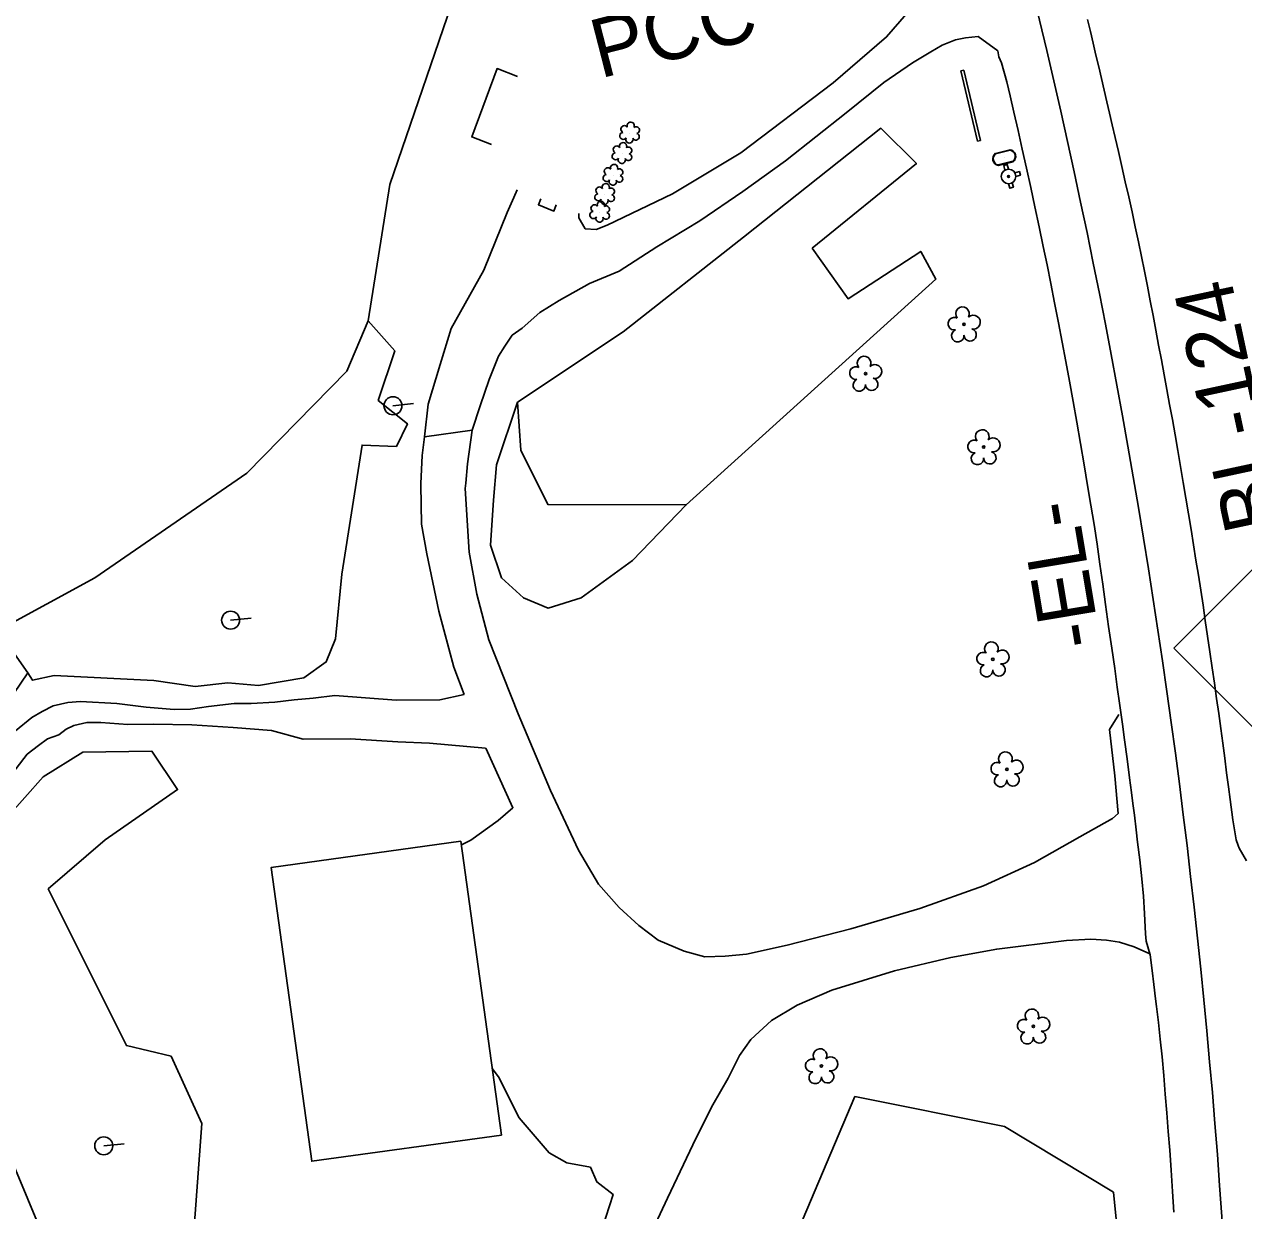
# Model space of a CAD drawing. Extents: x 471894 to 476235, y 503501 to 507878.
# Drawn here: x 474193.2 to 474525.3, y 504600 to 504923.2 of the extents above; entities that cross this region are included whole.
import ezdxf

# ---------------------------------------------------------------- set-up
doc = ezdxf.new("R2010")
doc.units = 0
for name, color, linetype in [('CTL Secondary Horizontal and Vertical CELL', 7, 'Continuous'), ('CTL Secondary Horizontal and Vertical Text', 7, 'Continuous'), ('Exist Building Metal Canopy', 7, 'Continuous'), ('Exist Horizontal Alignment', 7, 'Continuous'), ('Exist Horizontal Alignment Direction Label', 7, 'Continuous'), ('Exist Other Culture Area Outline', 7, 'Continuous'), ('Exist Roads EOP', 7, 'Continuous'), ('Exist Roads EOP Other', 7, 'Continuous'), ('Exist Roads Soil', 7, 'Continuous'), ('Exist Structure Minor Head and End Wall', 7, 'Continuous'), ('Exist Utilities Power Pole CELL', 7, 'Continuous'), ('Exist Utilities Water Fire Hydrant CELL', 7, 'Continuous'), ('Exist Utilities Water Meter CELL', 7, 'Continuous'), ('Exist Vegetation Hedge Row', 7, 'Continuous'), ('Exist Vegetation Shrub CELL', 7, 'Continuous'), ('Exist Vegetation Tree CELL', 7, 'Continuous'), ('Exist Vegetation Woods Line', 7, 'Continuous')]:
    doc.layers.add(name, color=color, linetype=linetype)

msp = doc.modelspace()

# ---------------------------------------------------------------- linework, layer by layer
at = {"layer": 'CTL Secondary Horizontal and Vertical CELL'}
msp.add_lwpolyline([(474506.26, 504753.23), (474532.47, 504779.43), (474558.72, 504753.18), (474532.51, 504726.98)], close=True, dxfattribs=at)
at = {"layer": 'Exist Building Metal Canopy'}
msp.add_lwpolyline([(474312.1, 504700.6), (474323.15, 504620.54), (474271.47, 504613.41), (474260.43, 504693.48)], close=True, dxfattribs=at)
at = {"layer": 'Exist Horizontal Alignment'}
msp.add_arc((472536.78, 504463.34), 1987.17, 358.7675, 14.39186, dxfattribs=at)
at = {"layer": 'Exist Other Culture Area Outline'}
for points in [[(474327.49, 504908.96), (474321.96, 504911.14), (474315.07, 504892.53), (474320.47, 504890.46)], [(474338.07, 504874.06), (474337.44, 504872.33), (474333.21, 504874.07), (474333.89, 504875.65)]]:
    msp.add_lwpolyline(points, dxfattribs=at)
at = {"layer": 'Exist Roads EOP'}
for points in [[(474482.78, 504924.51), (474483.55, 504921.3), (474484.32, 504918.08), (474485.08, 504914.86), (474485.84, 504911.63), (474486.59, 504908.43), (474487.32, 504905.26), (474488.05, 504902.13), (474488.77, 504899.04), (474489.52, 504895.83), (474490.32, 504892.34), (474491.19, 504888.57), (474492.11, 504884.51), (474493.06, 504880.34), (474493.99, 504876.19), (474494.9, 504872.09), (474495.79, 504868.02), (474496.65, 504863.97), (474497.49, 504859.94), (474498.3, 504855.92), (474499.08, 504851.91), (474499.85, 504847.9), (474500.61, 504843.88), (474501.37, 504839.85), (474502.13, 504835.81), (474502.89, 504831.77), (474503.65, 504827.72), (474504.39, 504823.67), (474505.14, 504819.62), (474505.88, 504815.52), (474506.62, 504811.35), (474507.36, 504807.1), (474508.11, 504802.77), (474508.85, 504798.41), (474509.57, 504794.1), (474510.28, 504789.83), (474510.97, 504785.59), (474511.65, 504781.4), (474512.32, 504777.24), (474512.97, 504773.13), (474513.6, 504769.05), (474514.23, 504764.96), (474514.86, 504760.79), (474515.49, 504756.54), (474516.12, 504752.22), (474516.74, 504747.9), (474517.34, 504743.66), (474517.93, 504739.51), (474518.5, 504735.43), (474519.05, 504731.38), (474519.6, 504727.34), (474520.13, 504723.3), (474520.65, 504719.25), (474521.15, 504715.41), (474521.6, 504712), (474522.35, 504706.45), (474523.22, 504701.02), (474523.76, 504699.47), (474524.11, 504698.7), (474526.11, 504695.31)], [(474506.3, 504599.55), (474505.93, 504605.16), (474505.54, 504610.97), (474505.15, 504616.45), (474504.74, 504621.57), (474504.34, 504626.63), (474503.95, 504631.69), (474503.52, 504636.77), (474503.06, 504641.84), (474502.58, 504646.69), (474502.08, 504651.27), (474501.56, 504655.59), (474501.3, 504657.65), (474500.8, 504661.61), (474500.37, 504665.37), (474499.83, 504669.71), (474498.78, 504673.41), (474498.54, 504675.41), (474498.32, 504680.95), (474498.05, 504685.61), (474497.6, 504690.4), (474497.01, 504695.59), (474496.42, 504700.4), (474496.01, 504703.76), (474495.55, 504707.7), (474495.14, 504710.91), (474494.75, 504713.88), (474494.21, 504717.93), (474493.53, 504723.04), (474492.84, 504728.23), (474492.27, 504732.5), (474491.48, 504738.29), (474490.88, 504742.61), (474490.18, 504747.67), (474489.39, 504753.27), (474488.53, 504759.18), (474487.68, 504765.09), (474486.91, 504770.67), (474486.16, 504776.11), (474485.37, 504781.56), (474484.54, 504786.96), (474483.7, 504792.22), (474482.81, 504797.57), (474481.83, 504803.23), (474480.83, 504809.03), (474479.85, 504814.79), (474478.87, 504820.46), (474477.87, 504826), (474476.86, 504831.39), (474475.86, 504836.64), (474474.85, 504841.89), (474473.81, 504847.29), (474472.77, 504852.61), (474471.76, 504857.65), (474470.72, 504862.7), (474469.6, 504868.06), (474468.45, 504873.5), (474467.3, 504878.79), (474466.16, 504883.99), (474465.01, 504889.18), (474463.87, 504894.29), (474462.73, 504899.24), (474461.68, 504903.75), (474460.76, 504907.52), (474459.34, 504912.77), (474459.02, 504913.56), (474458.62, 504914.33), (474458.33, 504916)]]:
    msp.add_lwpolyline(points, dxfattribs=at)
at = {"layer": 'Exist Roads EOP Other'}
for p, q in [((474326.55, 504875.99), (474327.4, 504878.12)), ((474315.2, 504812.65), (474302.17, 504810.79))]:
    msp.add_line(p, q, dxfattribs=at)
for points in [[(474345.92, 504867.53), (474348.98, 504867.32), (474351.93, 504868.46), (474369.71, 504876.99), (474388.35, 504888.21), (474413.53, 504907.31), (474428.05, 504919.81), (474436.49, 504929.49), (474441.42, 504937.69), (474444.56, 504945.08), (474446.91, 504953.55)], [(474315.2, 504812.65), (474317.34, 504819.3), (474319.78, 504826.45), (474322.37, 504832.77), (474324.1, 504835.56), (474326.08, 504838.49), (474328.8, 504840.43), (474333.61, 504844.69), (474338.85, 504847.94), (474347.15, 504852.57), (474355.17, 504855.94), (474365.42, 504862.56), (474377.22, 504869.67), (474388.89, 504877.71), (474400.51, 504885.98), (474417, 504899.13), (474427.29, 504907.38), (474435.09, 504912.72), (474440.11, 504915.76), (474443.17, 504917.56), (474446.84, 504919.04), (474449.51, 504919.52), (474452.99, 504919.92)], [(474458.33, 504916), (474452.99, 504919.92)], [(474302.17, 504810.79), (474303.22, 504819.7), (474306.45, 504830.52), (474309.42, 504840.34), (474318.35, 504856.19), (474324.71, 504871.97), (474326.55, 504875.99)], [(474344.24, 504871.71), (474344.24, 504870.47), (474345.92, 504867.53)]]:
    msp.add_lwpolyline(points, dxfattribs=at)
at = {"layer": 'Exist Roads Soil'}
for points in [[(474313.43, 504798.23), (474313.93, 504803.5), (474315.2, 504812.65)], [(474301.2, 504798.13), (474301.48, 504803.8), (474301.57, 504805.77), (474302.17, 504810.79)], [(474301.33, 504787.04), (474301.18, 504797.72), (474301.2, 504798.13)], [(474313.29, 504796.73), (474313.43, 504798.23)], [(474313.29, 504796.73), (474314.32, 504779.35), (474316.43, 504767.92), (474319.74, 504755.52), (474327.73, 504735.36), (474336.53, 504714.42), (474344.1, 504698.18), (474349.61, 504688.92), (474355.19, 504682.57), (474360.56, 504677.66), (474365.86, 504673.71), (474372.89, 504670.64), (474378.53, 504669.1), (474384.07, 504669.34), (474389.85, 504669.82), (474401, 504672.33), (474418.32, 504676.73), (474437.13, 504682.25), (474454.44, 504688.43), (474468.34, 504694.87), (474480.7, 504701.85), (474489.61, 504706.84), (474491.1, 504708.2), (474490.18, 504718.46), (474488.8, 504731.08), (474491.34, 504735.12)], [(474312.98, 504740.61), (474310.21, 504748.05), (474306.12, 504763.32), (474302.82, 504778.95), (474301.33, 504787.04)], [(474208.48, 504738.66), (474218.42, 504738.16), (474226.4, 504737.18), (474234.01, 504736.49), (474238.48, 504736.58), (474243.39, 504737.34), (474250.36, 504738.15), (474254.97, 504738.11), (474261.42, 504738.49), (474266.69, 504739.11), (474271.84, 504739.59), (474277.73, 504740.35)], [(474277.73, 504740.35), (474294.47, 504739.05), (474306.34, 504739.15), (474312.98, 504740.61)], [(474173.69, 504709.24), (474182.2, 504722.26), (474186.67, 504727.32), (474190.8, 504730.75), (474195.25, 504734.37), (474198.02, 504736), (474201.01, 504737.48), (474205.04, 504738.41), (474208.48, 504738.66)], [(474294.93, 504727.68), (474281.97, 504728.49), (474269.14, 504728.46), (474260.53, 504730.84), (474250.05, 504731.58), (474238.85, 504732.34), (474228.39, 504732.55), (474221.36, 504732.46), (474214, 504732.96), (474210.18, 504732.95), (474206.64, 504732.2)], [(474181.88, 504707.45), (474186.64, 504714.69), (474191, 504720.41), (474194, 504724.32), (474197.04, 504726.68), (474199.51, 504728.56), (474202.59, 504729.66), (474204.59, 504731.12), (474206.64, 504732.2)], [(474294.93, 504727.68), (474303.55, 504727.39), (474318.79, 504725.96)], [(474312.24, 504699.63), (474314.8, 504700.92), (474322.29, 504706.24), (474326.26, 504709.76), (474318.87, 504725.99)], [(474499.79, 504669.9), (474495.5, 504671.88), (474491.44, 504673.13), (474487.91, 504673.69), (474483.7, 504673.96), (474477.06, 504673.56), (474458.05, 504671.24), (474445.51, 504668.93), (474430.16, 504665.31), (474413.14, 504660.05), (474403.69, 504655.94), (474396.66, 504651.82), (474391.06, 504646.58), (474387.98, 504642.25), (474384.92, 504636.03), (474380.68, 504628.81), (474376.15, 504619.77), (474368.33, 504603.4), (474361.1, 504587.83)], [(474350.55, 504595.06), (474353.61, 504604.35), (474349.13, 504607.77), (474347.36, 504611.83), (474340.91, 504612.96), (474336.12, 504615.74), (474327.96, 504625.26), (474322.3, 504636.44), (474320.65, 504638.66)]]:
    msp.add_lwpolyline(points, dxfattribs=at)
at = {"layer": 'Exist Structure Minor Head and End Wall'}
for p, q in [((474448.23, 504910.57), (474449.04, 504910.76)), ((474452.77, 504891.37), (474448.23, 504910.57)), ((474453.58, 504891.56), (474449.04, 504910.76)), ((474452.77, 504891.37), (474453.58, 504891.56))]:
    msp.add_line(p, q, dxfattribs=at)
at = {"layer": 'Exist Utilities Power Pole CELL'}
for p, q in [((474293.6, 504819.29), (474299.19, 504819.86)), ((474293.6, 504819.29), (474293.6, 504819.29)), ((474249.38, 504760.86), (474254.97, 504761.43)), ((474249.38, 504760.86), (474249.38, 504760.86)), ((474214.81, 504617.63), (474220.4, 504618.2)), ((474214.81, 504617.63), (474214.81, 504617.63))]:
    msp.add_line(p, q, dxfattribs=at)
for centre in [(474293.6, 504819.29), (474249.38, 504760.86), (474214.81, 504617.63)]:
    msp.add_circle(centre, 2.45, dxfattribs=at)
at = {"layer": 'Exist Utilities Water Fire Hydrant CELL'}
msp.add_line((474461.26, 504881.77), (474461.26, 504881.77), dxfattribs=at)
for points in [[(474461.26, 504883.75), (474460.93, 504884.99), (474459.94, 504884.73), (474460.28, 504883.46)], [(474463.24, 504881.77), (474464.48, 504882.1), (474464.22, 504883.09), (474462.97, 504882.76)], [(474462.25, 504880.05), (474462.58, 504878.81), (474461.59, 504878.54), (474461.25, 504879.81)]]:
    msp.add_lwpolyline(points, dxfattribs=at)
for radius in [1.98, 0.243]:
    msp.add_circle((474461.26, 504881.77), radius, dxfattribs=at)
at = {"layer": 'Exist Utilities Water Meter CELL'}
msp.add_line((474460.1, 504886.91), (474460.1, 504886.91), dxfattribs=at)
for points in [[(474457.71, 504888.06), (474461.66, 504889.06)], [(474457.74, 504887.93), (474461.69, 504888.93)], [(474462.46, 504885.9), (474458.48, 504884.89)], [(474462.49, 504885.77), (474458.52, 504884.76)]]:
    msp.add_lwpolyline(points, dxfattribs=at)
for centre, radius, start, end in [((474461.35, 504887.23), 1.86, 307.8277, 80.4878), ((474461.36, 504887.23), 1.73, 309.3066, 79.0522), ((474458.83, 504886.59), 1.86, 127.3574, 260.1588), ((474458.84, 504886.59), 1.73, 129.4803, 257.9618)]:
    msp.add_arc(centre, radius, start, end, dxfattribs=at)
at = {"layer": 'Exist Vegetation Hedge Row'}
msp.add_line((474321.81, 504803.16), (474327.53, 504820.22), dxfattribs=at)
for points in [[(474286.83, 504842.4), (474294.1, 504834.23), (474289.59, 504820.73), (474297.52, 504814.39), (474294.53, 504808.15), (474285.17, 504808.57), (474279.69, 504773.36)], [(474373.46, 504792.27), (474358.83, 504777.14), (474344.84, 504766.94), (474335.84, 504764.15), (474329.11, 504766.93), (474323.14, 504772.43), (474320.13, 504781.31), (474320.96, 504793.52), (474321.81, 504803.16)], [(474279.69, 504773.36), (474277.91, 504755.75), (474275.43, 504749.49), (474269.29, 504745.16), (474257.01, 504743.09), (474248.61, 504743.78), (474239.74, 504742.77), (474228.49, 504744.43)], [(474228.49, 504744.43), (474201.3, 504745.76), (474195.41, 504744.48), (474194.18, 504746.5)], [(474139.09, 504552.19), (474151.55, 504629.91), (474164.24, 504664.12), (474188.29, 504706.88), (474198.29, 504718.2), (474209.11, 504724.87), (474227.92, 504725.12), (474234.92, 504714.69), (474215.17, 504701.05), (474199.72, 504687.62), (474221, 504644.93), (474233.14, 504642.04), (474241.52, 504623.67), (474239.57, 504596.64), (474237.63, 504586.96)]]:
    msp.add_lwpolyline(points, dxfattribs=at)
at = {"layer": 'Exist Vegetation Shrub CELL'}
for p, q in [((474358.12, 504893.54), (474358.12, 504893.54)), ((474356.04, 504887.97), (474356.04, 504887.97)), ((474353.59, 504882.04), (474353.59, 504882.04)), ((474351.32, 504876.8), (474351.32, 504876.8)), ((474349.98, 504871.96), (474349.98, 504871.96))]:
    msp.add_line(p, q, dxfattribs=at)
for centre, radius, start, end in [((474356.64, 504894.66), 0.968, 35.8908, 245.4216), ((474358.35, 504895.58), 0.99, 334.8391, 200.4717), ((474356.32, 504892.83), 0.955, 95.1099, 327.9534), ((474357.99, 504891.85), 0.984, 151.2797, 21.387), ((474359.76, 504892.61), 0.937, 204.9913, 73.4601), ((474359.79, 504894.4), 0.929, 284.4567, 126.0861), ((474354.56, 504889.1), 0.968, 35.8908, 245.4216), ((474356.27, 504890.01), 0.99, 334.8391, 200.4717), ((474357.71, 504888.84), 0.929, 284.4567, 126.0861), ((474354.24, 504887.27), 0.955, 95.1099, 327.9534), ((474355.91, 504886.29), 0.984, 151.2797, 21.387), ((474357.68, 504887.04), 0.937, 204.9913, 73.4601), ((474351.79, 504881.34), 0.955, 95.1099, 327.9534), ((474352.11, 504883.17), 0.968, 35.8908, 245.4216), ((474353.82, 504884.08), 0.99, 334.8391, 200.4717), ((474355.27, 504882.91), 0.929, 284.4567, 126.0861), ((474349.84, 504877.93), 0.968, 35.8908, 245.4216), ((474351.55, 504878.84), 0.99, 334.8391, 200.4717), ((474353.47, 504880.36), 0.984, 151.2797, 21.387), ((474355.23, 504881.11), 0.937, 204.9913, 73.4601), ((474349.52, 504876.1), 0.955, 95.1099, 327.9534), ((474351.2, 504875.12), 0.984, 151.2797, 21.387), ((474352.96, 504875.87), 0.937, 204.9913, 73.4601), ((474353, 504877.67), 0.929, 284.4567, 126.0861), ((474348.18, 504871.25), 0.955, 95.1099, 327.9534), ((474348.49, 504873.08), 0.968, 35.8908, 245.4216), ((474350.21, 504874), 0.99, 334.8391, 200.4717), ((474351.65, 504872.82), 0.929, 284.4567, 126.0861), ((474349.85, 504870.27), 0.984, 151.2797, 21.387), ((474351.61, 504871.03), 0.937, 204.9913, 73.4601)]:
    msp.add_arc(centre, radius, start, end, dxfattribs=at)
at = {"layer": 'Exist Vegetation Tree CELL'}
for p, q in [((474449.12, 504841.49), (474449.12, 504841.49)), ((474422.31, 504828.04), (474422.31, 504828.04)), ((474454.49, 504808.02), (474454.49, 504808.02)), ((474456.98, 504750.22), (474456.98, 504750.22)), ((474460.8, 504720.25), (474460.8, 504720.25)), ((474468.03, 504650.17), (474468.03, 504650.17)), ((474410.31, 504639.35), (474410.31, 504639.35))]:
    msp.add_line(p, q, dxfattribs=at)
for centre in [(474449.12, 504841.49), (474422.31, 504828.04), (474454.49, 504808.02), (474456.98, 504750.22), (474460.8, 504720.25), (474468.03, 504650.17), (474410.31, 504639.35)]:
    msp.add_circle(centre, 0.326, dxfattribs=at)
for centre, radius, start, end in [((474448.73, 504844.36), 1.86, 330.1651, 219.7134), ((474446.51, 504841.64), 1.73, 62.6636, 279.3457), ((474451.67, 504842.08), 1.9, 257.1011, 134.1999), ((474447.41, 504838.37), 1.69, 111.5671, 6.231), ((474450.79, 504838.59), 1.7, 181.2822, 74.56), ((474421.92, 504830.91), 1.86, 330.1651, 219.7134), ((474419.7, 504828.19), 1.73, 62.6636, 279.3457), ((474424.85, 504828.63), 1.9, 257.1011, 134.1999), ((474420.6, 504824.92), 1.69, 111.5671, 6.231), ((474423.98, 504825.14), 1.7, 181.2822, 74.56), ((474454.11, 504810.89), 1.86, 330.1651, 219.7134), ((474451.89, 504808.17), 1.73, 62.6636, 279.3457), ((474457.04, 504808.61), 1.9, 257.1011, 134.1999), ((474452.79, 504804.9), 1.69, 111.5671, 6.231), ((474456.17, 504805.12), 1.7, 181.2822, 74.56), ((474456.59, 504753.1), 1.86, 330.1651, 219.7134), ((474459.53, 504750.81), 1.9, 257.1011, 134.1999), ((474454.37, 504750.38), 1.73, 62.6636, 279.3457), ((474455.27, 504747.1), 1.69, 111.5671, 6.231), ((474458.65, 504747.32), 1.7, 181.2822, 74.56), ((474460.42, 504723.12), 1.86, 330.1651, 219.7134), ((474463.35, 504720.84), 1.9, 257.1011, 134.1999), ((474458.2, 504720.4), 1.73, 62.6636, 279.3457), ((474459.1, 504717.13), 1.69, 111.5671, 6.231), ((474462.47, 504717.35), 1.7, 181.2822, 74.56), ((474467.64, 504653.05), 1.86, 330.1651, 219.7134), ((474465.42, 504650.33), 1.73, 62.6636, 279.3457), ((474470.57, 504650.76), 1.9, 257.1011, 134.1999), ((474466.32, 504647.05), 1.69, 111.5671, 6.231), ((474469.7, 504647.27), 1.7, 181.2822, 74.56), ((474409.92, 504642.23), 1.86, 330.1651, 219.7134), ((474407.7, 504639.51), 1.73, 62.6636, 279.3457), ((474412.86, 504639.94), 1.9, 257.1011, 134.1999), ((474408.6, 504636.23), 1.69, 111.5671, 6.231), ((474411.98, 504636.45), 1.7, 181.2822, 74.56)]:
    msp.add_arc(centre, radius, start, end, dxfattribs=at)
at = {"layer": 'Exist Vegetation Woods Line'}
for points in [[(474039.74, 505231.39), (474070.64, 505227.57), (474100.38, 505210.48), (474145.85, 505197.49), (474221.93, 505186.17), (474248.45, 505176.22), (474277.09, 505162.04), (474333.09, 505118.27), (474352.71, 505084.66), (474349.72, 505047.44), (474370.59, 505001.39), (474331.17, 504970.24), (474311.76, 504935.08), (474292.73, 504879.6), (474286.83, 504842.4), (474281, 504828.7), (474253.76, 504800.95), (474212.37, 504772.4), (474185.95, 504758.02), (474194.18, 504746.5), (474168.72, 504709.09), (474147.17, 504667.02), (474132.12, 504653.24), (474125.76, 504660.6)], [(474328.42, 504807.14), (474327.53, 504820.22), (474356.3, 504839.46), (474389.04, 504865.23), (474426.44, 504894.91), (474436.15, 504885.28), (474407.79, 504862.26)], [(474407.79, 504862.26), (474417.55, 504848.46), (474437.34, 504861.33), (474441.46, 504853.79), (474373.46, 504792.27), (474335.76, 504792.4), (474328.42, 504807.14)], [(474139.09, 504552.19), (474155.17, 504560.15), (474156.57, 504605.34), (474167.19, 504647.42), (474176.84, 504644.56), (474221.5, 504537.29), (474227.36, 504512.7), (474212.61, 504480.68), (474221.58, 504463.05), (474231.43, 504463.83), (474264.02, 504383.76)], [(474363.17, 504428.14), (474370.99, 504446.82), (474352.61, 504495.07), (474363.26, 504527.87), (474424.56, 504558.83), (474431.82, 504570.68), (474421.04, 504587.28), (474400.87, 504566.59), (474393.26, 504569.34), (474419.43, 504631.05), (474460.12, 504622.89), (474489.82, 504604.99), (474496.17, 504541.35), (474498.87, 504449.99), (474498.04, 504421.91)]]:
    msp.add_lwpolyline(points, dxfattribs=at)

# ---------------------------------------------------------------- texts
at = {"layer": 'CTL Secondary Horizontal and Vertical Text'}
msp.add_text('BL-124', height=16, rotation=102.1189, dxfattribs=at).set_placement((474536.23, 504786.98))
at = {"layer": 'Exist Horizontal Alignment'}
msp.add_text('PCC', height=16, rotation=14.3919, dxfattribs=at).set_placement((474349.99, 504908.42))
at = {"layer": 'Exist Horizontal Alignment Direction Label'}
msp.add_text('-EL-', height=16, rotation=99.5189, dxfattribs=at).set_placement((474486.44, 504754.4))

doc.saveas('drawing.dxf')
